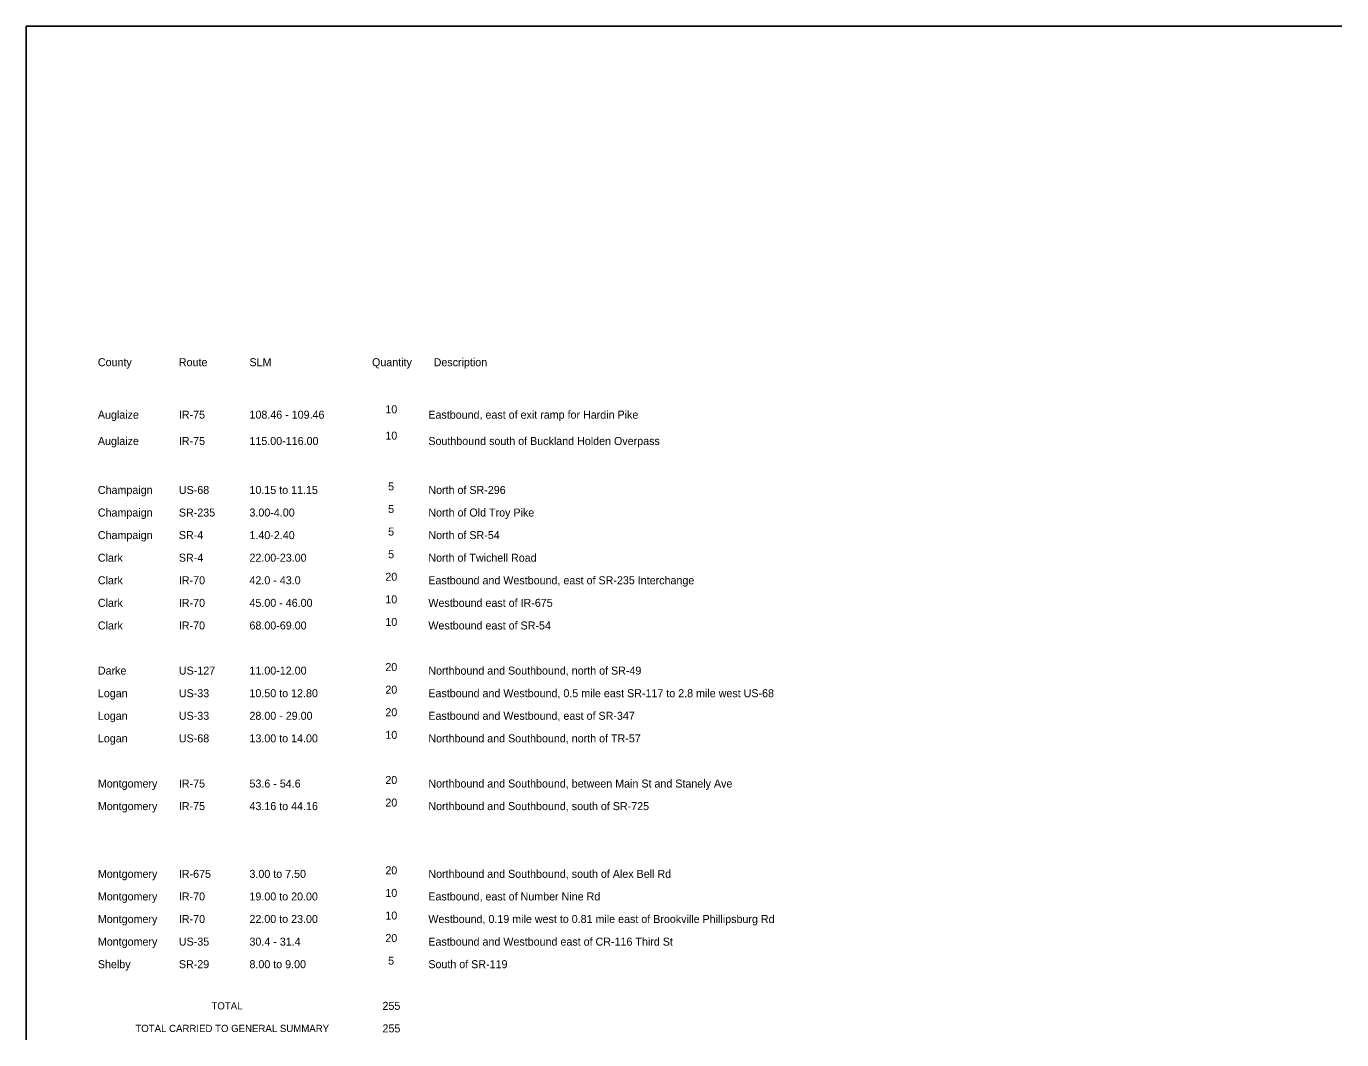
# Model space of a CAD drawing. Extents: x -26.8 to 34, y 0 to 22.
# Drawn here: x -26.82 to -3.81, y 3.76 to 21.5 of the extents above; entities that cross this region are included whole.
import ezdxf

# ---------------------------------------------------------------- set-up
doc = ezdxf.new("R2010")
doc.units = 0
doc.layers.add('Default', color=7, linetype='Continuous')
doc.layers.add('SH_Data', color=7, linetype='Continuous')

msp = doc.modelspace()

# ---------------------------------------------------------------- linework, layer by layer
at = {"layer": 'SH_Data'}
for q in [(-3.807, 21.5), (-26.817, 3.761)]:
    msp.add_line((-26.817, 21.5), q, dxfattribs=at)

# ---------------------------------------------------------------- texts
at = {"layer": 'Default'}
for s, height, p in [('County', 0.14, (-25.565, 15.55)), ('Route', 0.14, (-24.148, 15.55)), ('SLM', 0.14, (-22.913, 15.55)), ('Quantity', 0.14, (-20.769, 15.55)), ('Description', 0.14, (-19.691, 15.55)), ('Auglaize', 0.14, (-25.565, 14.632)), ('IR-75', 0.14, (-24.148, 14.632)), ('108.46 - 109.46', 0.14, (-22.913, 14.632)), ('10', 0.14, (-20.536, 14.726)), ('Eastbound, east of exit ramp for Hardin Pike', 0.14, (-19.784, 14.632)), ('Auglaize', 0.14, (-25.565, 14.171)), ('IR-75', 0.14, (-24.148, 14.171)), ('115.00-116.00', 0.14, (-22.913, 14.171)), ('10', 0.14, (-20.536, 14.265)), ('Southbound south of Buckland Holden Overpass', 0.14, (-19.784, 14.171)), ('Champaign', 0.14, (-25.565, 13.314)), ('US-68', 0.14, (-24.148, 13.314)), ('10.15 to 11.15', 0.14, (-22.913, 13.314)), ('5', 0.14, (-20.488, 13.376)), ('North of SR-296', 0.14, (-19.784, 13.314)), ('5', 0.14, (-20.488, 12.981)), ('Champaign', 0.14, (-25.565, 12.919)), ('SR-235', 0.14, (-24.148, 12.919)), ('3.00-4.00', 0.14, (-22.913, 12.919)), ('North of Old Troy Pike', 0.14, (-19.784, 12.919)), ('Champaign', 0.14, (-25.565, 12.524)), ('SR-4', 0.14, (-24.148, 12.524)), ('1.40-2.40', 0.14, (-22.913, 12.524)), ('5', 0.14, (-20.488, 12.585)), ('North of SR-54', 0.14, (-19.784, 12.524)), ('Clark', 0.14, (-25.565, 12.128)), ('SR-4', 0.14, (-24.148, 12.128)), ('22.00-23.00', 0.14, (-22.913, 12.128)), ('5', 0.14, (-20.488, 12.19)), ('North of Twichell Road', 0.14, (-19.784, 12.128)), ('Clark', 0.14, (-25.565, 11.733)), ('IR-70', 0.14, (-24.148, 11.733)), ('42.0 - 43.0', 0.14, (-22.913, 11.733)), ('20', 0.14, (-20.536, 11.795)), ('Eastbound and Westbound, east of SR-235 Interchange', 0.14, (-19.784, 11.733)), ('10', 0.14, (-20.536, 11.399)), ('Clark', 0.14, (-25.565, 11.338)), ('IR-70', 0.14, (-24.148, 11.338)), ('45.00 - 46.00', 0.14, (-22.913, 11.338)), ('Westbound east of IR-675', 0.14, (-19.784, 11.338)), ('Clark', 0.14, (-25.565, 10.942)), ('IR-70', 0.14, (-24.148, 10.942)), ('68.00-69.00', 0.14, (-22.913, 10.942)), ('10', 0.14, (-20.536, 11.004)), ('Westbound east of SR-54', 0.14, (-19.784, 10.942)), ('20', 0.14, (-20.536, 10.214)), ('Darke', 0.14, (-25.565, 10.152)), ('US-127', 0.14, (-24.148, 10.152)), ('11.00-12.00', 0.14, (-22.913, 10.152)), ('Northbound and Southbound, north of SR-49', 0.14, (-19.784, 10.152)), ('Logan', 0.14, (-25.565, 9.756)), ('US-33', 0.14, (-24.148, 9.756)), ('10.50 to 12.80', 0.14, (-22.913, 9.756)), ('20', 0.14, (-20.536, 9.818)), ('Eastbound and Westbound, 0.5 mile east SR-117 to 2.8 mile west US-68', 0.14, (-19.784, 9.756)), ('Logan', 0.14, (-25.565, 9.361)), ('US-33', 0.14, (-24.148, 9.361)), ('28.00 - 29.00', 0.14, (-22.913, 9.361)), ('20', 0.14, (-20.536, 9.423)), ('Eastbound and Westbound, east of SR-347', 0.14, (-19.784, 9.361)), ('Logan', 0.14, (-25.565, 8.966)), ('US-68', 0.14, (-24.148, 8.966)), ('13.00 to 14.00', 0.14, (-22.913, 8.966)), ('10', 0.14, (-20.536, 9.028)), ('Northbound and Southbound, north of TR-57', 0.14, (-19.784, 8.966)), ('Montgomery', 0.14, (-25.565, 8.175)), ('IR-75', 0.14, (-24.148, 8.175)), ('53.6 - 54.6', 0.14, (-22.913, 8.175)), ('20', 0.14, (-20.536, 8.237)), ('Northbound and Southbound, between Main St and Stanely Ave', 0.14, (-19.784, 8.175)), ('Montgomery', 0.14, (-25.565, 7.78)), ('IR-75', 0.14, (-24.148, 7.78)), ('43.16 to 44.16', 0.14, (-22.913, 7.78)), ('20', 0.14, (-20.536, 7.842)), ('Northbound and Southbound, south of SR-725', 0.14, (-19.784, 7.78)), ('Montgomery', 0.14, (-25.565, 6.594)), ('IR-675', 0.14, (-24.148, 6.594)), ('3.00 to 7.50', 0.14, (-22.913, 6.594)), ('20', 0.14, (-20.536, 6.656)), ('Northbound and Southbound, south of Alex Bell Rd', 0.14, (-19.784, 6.594)), ('Montgomery', 0.14, (-25.565, 6.199)), ('IR-70', 0.14, (-24.148, 6.199)), ('19.00 to 20.00', 0.14, (-22.913, 6.199)), ('10', 0.14, (-20.536, 6.261)), ('Eastbound, east of Number Nine Rd', 0.14, (-19.784, 6.199)), ('10', 0.14, (-20.536, 5.865)), ('Montgomery', 0.14, (-25.565, 5.804)), ('IR-70', 0.14, (-24.148, 5.804)), ('22.00 to 23.00', 0.14, (-22.913, 5.804)), ('Westbound, 0.19 mile west to 0.81 mile east of Brookville Phillipsburg Rd', 0.14, (-19.784, 5.804)), ('Montgomery', 0.14, (-25.565, 5.408)), ('US-35', 0.14, (-24.148, 5.408)), ('30.4 - 31.4', 0.14, (-22.913, 5.408)), ('20', 0.14, (-20.536, 5.47)), ('Eastbound and Westbound east of CR-116 Third St', 0.14, (-19.784, 5.408)), ('Shelby', 0.14, (-25.565, 5.013)), ('SR-29', 0.14, (-24.148, 5.013)), ('8.00 to 9.00', 0.14, (-22.913, 5.013)), ('5', 0.14, (-20.488, 5.075)), ('South of SR-119', 0.14, (-19.784, 5.013)), ('TOTAL', 0.126, (-23.578, 4.291)), ('255', 0.14, (-20.586, 4.284)), ('TOTAL CARRIED TO GENERAL SUMMARY', 0.126, (-24.909, 3.896)), ('255', 0.14, (-20.586, 3.889))]:
    msp.add_text(s, height=height, dxfattribs=at).set_placement(p)

doc.saveas('drawing.dxf')
